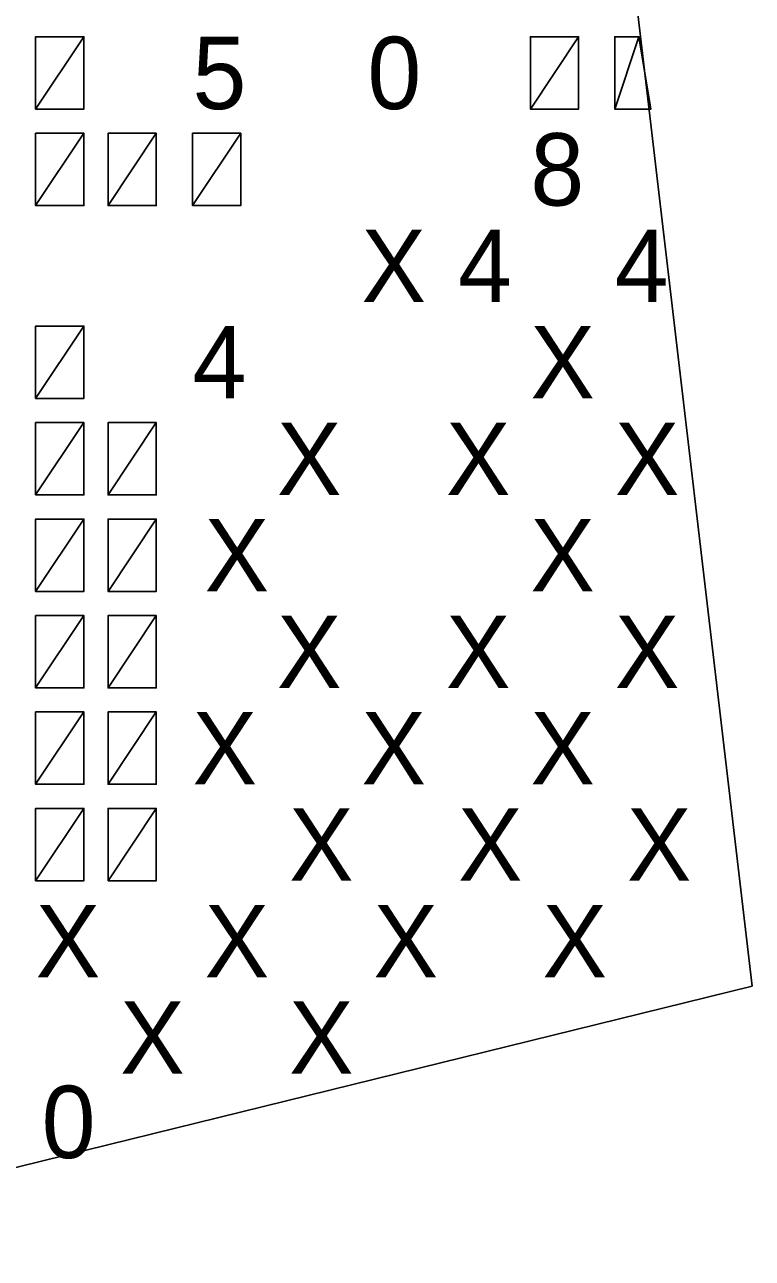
# Model space of a CAD drawing. Extents: x 0 to 34, y -1.2 to 22.
# Drawn here: x 3.5971 to 3.7687, y 4.3382 to 4.6293 of the extents above; entities that cross this region are included whole.
import ezdxf

# ---------------------------------------------------------------- set-up
doc = ezdxf.new("R2010")
doc.units = 0
doc.layers.add('Default', color=7, linetype='Continuous')

msp = doc.modelspace()

# ---------------------------------------------------------------- linework, layer by layer
at = {"layer": 'Default'}
for p, q in [((3.71021, 4.89963), (3.76865, 4.40245)), ((3.59966, 4.62644), (3.59966, 4.60937)), ((3.61104, 4.62644), (3.59966, 4.62644)), ((3.61104, 4.60937), (3.61104, 4.62644)), ((3.72769, 4.62644), (3.71631, 4.62644)), ((3.71631, 4.62644), (3.71631, 4.60937)), ((3.72769, 4.60937), (3.72769, 4.62644)), ((3.73623, 4.62644), (3.74192, 4.62644)), ((3.73623, 4.60937), (3.73623, 4.62644)), ((3.59966, 4.60937), (3.61104, 4.60937)), ((3.71631, 4.60937), (3.72769, 4.60937)), ((3.73623, 4.60937), (3.74476, 4.60937)), ((3.61104, 4.60368), (3.59966, 4.60368)), ((3.59966, 4.60368), (3.59966, 4.58661)), ((3.61104, 4.58661), (3.61104, 4.60368)), ((3.61673, 4.60368), (3.61673, 4.58661)), ((3.62811, 4.60368), (3.61673, 4.60368)), ((3.62811, 4.58661), (3.62811, 4.60368)), ((3.64803, 4.60368), (3.63665, 4.60368)), ((3.63665, 4.60368), (3.63665, 4.58661)), ((3.64803, 4.58661), (3.64803, 4.60368)), ((3.59966, 4.58661), (3.61104, 4.58661)), ((3.61673, 4.58661), (3.62811, 4.58661)), ((3.63665, 4.58661), (3.64803, 4.58661)), ((3.59966, 4.55816), (3.59966, 4.54109)), ((3.61104, 4.55816), (3.59966, 4.55816)), ((3.61104, 4.54109), (3.61104, 4.55816)), ((3.59966, 4.54109), (3.61104, 4.54109)), ((3.61104, 4.53539), (3.59966, 4.53539)), ((3.59966, 4.53539), (3.59966, 4.51832)), ((3.61104, 4.51832), (3.61104, 4.53539)), ((3.61673, 4.53539), (3.61673, 4.51832)), ((3.62811, 4.53539), (3.61673, 4.53539)), ((3.62811, 4.51832), (3.62811, 4.53539)), ((3.59966, 4.51832), (3.61104, 4.51832)), ((3.61673, 4.51832), (3.62811, 4.51832)), ((3.61104, 4.51263), (3.59966, 4.51263)), ((3.59966, 4.51263), (3.59966, 4.49556)), ((3.61104, 4.49556), (3.61104, 4.51263)), ((3.62811, 4.51263), (3.61673, 4.51263)), ((3.61673, 4.51263), (3.61673, 4.49556)), ((3.62811, 4.49556), (3.62811, 4.51263)), ((3.59966, 4.49556), (3.61104, 4.49556)), ((3.61673, 4.49556), (3.62811, 4.49556)), ((3.59966, 4.48987), (3.59966, 4.4728)), ((3.61104, 4.48987), (3.59966, 4.48987)), ((3.61104, 4.4728), (3.61104, 4.48987)), ((3.62811, 4.48987), (3.61673, 4.48987)), ((3.61673, 4.48987), (3.61673, 4.4728)), ((3.62811, 4.4728), (3.62811, 4.48987)), ((3.59966, 4.4728), (3.61104, 4.4728)), ((3.61673, 4.4728), (3.62811, 4.4728)), ((3.61104, 4.46711), (3.59966, 4.46711)), ((3.59966, 4.46711), (3.59966, 4.45004)), ((3.61104, 4.45004), (3.61104, 4.46711)), ((3.61673, 4.46711), (3.61673, 4.45004)), ((3.62811, 4.46711), (3.61673, 4.46711)), ((3.62811, 4.45004), (3.62811, 4.46711)), ((3.59966, 4.45004), (3.61104, 4.45004)), ((3.61673, 4.45004), (3.62811, 4.45004)), ((3.61104, 4.44435), (3.59966, 4.44435)), ((3.59966, 4.44435), (3.59966, 4.42728)), ((3.61104, 4.42728), (3.61104, 4.44435)), ((3.61673, 4.44435), (3.61673, 4.42728)), ((3.62811, 4.44435), (3.61673, 4.44435)), ((3.62811, 4.42728), (3.62811, 4.44435)), ((3.59966, 4.42728), (3.61104, 4.42728)), ((3.61673, 4.42728), (3.62811, 4.42728)), ((3.76865, 4.40245), (3.50784, 4.33819))]:
    msp.add_line(p, q, dxfattribs=at)
for points in [[(3.59966, 4.60937), (3.59966, 4.62644), (3.61104, 4.62644)], [(3.61104, 4.62644), (3.61104, 4.60937), (3.59966, 4.60937)], [(3.61104, 4.62644), (3.61104, 4.62644), (3.61104, 4.62644)], [(3.71631, 4.60937), (3.71631, 4.62644), (3.72769, 4.62644)], [(3.72769, 4.62644), (3.72769, 4.60937), (3.71631, 4.60937)], [(3.73623, 4.60937), (3.73623, 4.62644), (3.74192, 4.62644)], [(3.74192, 4.62644), (3.74476, 4.60937), (3.73623, 4.60937)], [(3.61104, 4.60368), (3.61104, 4.58661), (3.59966, 4.58661)], [(3.59966, 4.58661), (3.59966, 4.60368), (3.61104, 4.60368)], [(3.61104, 4.60368), (3.61104, 4.60368), (3.61104, 4.60368)], [(3.62811, 4.60368), (3.62811, 4.58661), (3.61673, 4.58661)], [(3.61673, 4.58661), (3.61673, 4.60368), (3.62811, 4.60368)], [(3.63665, 4.58661), (3.63665, 4.60368), (3.64803, 4.60368)], [(3.64803, 4.60368), (3.64803, 4.58661), (3.63665, 4.58661)], [(3.59966, 4.54109), (3.59966, 4.55816), (3.61104, 4.55816)], [(3.59966, 4.54109), (3.61104, 4.54109), (3.61104, 4.55816)], [(3.59966, 4.51832), (3.61104, 4.51832), (3.61104, 4.53539)], [(3.59966, 4.51832), (3.59966, 4.53539), (3.61104, 4.53539)], [(3.62811, 4.53539), (3.62811, 4.51832), (3.61673, 4.51832)], [(3.61673, 4.51832), (3.61673, 4.53539), (3.62811, 4.53539)], [(3.59966, 4.49556), (3.61104, 4.49556), (3.61104, 4.51263)], [(3.59966, 4.49556), (3.59966, 4.51263), (3.61104, 4.51263)], [(3.61673, 4.49556), (3.61673, 4.51263), (3.62811, 4.51263)], [(3.62811, 4.51263), (3.62811, 4.49556), (3.61673, 4.49556)], [(3.59966, 4.4728), (3.59966, 4.48987), (3.61104, 4.48987)], [(3.61104, 4.48987), (3.61104, 4.4728), (3.59966, 4.4728)], [(3.61104, 4.48987), (3.61104, 4.48987), (3.61104, 4.48987)], [(3.61673, 4.4728), (3.61673, 4.48987), (3.62811, 4.48987)], [(3.62811, 4.48987), (3.62811, 4.4728), (3.61673, 4.4728)], [(3.61104, 4.46711), (3.61104, 4.45004), (3.59966, 4.45004)], [(3.59966, 4.45004), (3.59966, 4.46711), (3.61104, 4.46711)], [(3.61104, 4.46711), (3.61104, 4.46711), (3.61104, 4.46711)], [(3.62811, 4.46711), (3.62811, 4.45004), (3.61673, 4.45004)], [(3.61673, 4.45004), (3.61673, 4.46711), (3.62811, 4.46711)], [(3.59966, 4.42728), (3.59966, 4.44435), (3.61104, 4.44435)], [(3.61104, 4.44435), (3.61104, 4.42728), (3.59966, 4.42728)], [(3.61673, 4.42728), (3.61673, 4.44435), (3.62811, 4.44435)], [(3.61673, 4.42728), (3.62811, 4.42728), (3.62811, 4.44435)]]:
    msp.add_lwpolyline(points, close=True, dxfattribs=at)

# ---------------------------------------------------------------- texts
for s, p in [('5', (3.63665, 4.60937)), ('0', (3.6779, 4.60937)), ('8', (3.71631, 4.58661)), ('X', (3.67648, 4.56385)), ('4', (3.69924, 4.56385)), ('4', (3.73623, 4.56385)), ('4', (3.63665, 4.54109)), ('X', (3.71631, 4.54109)), ('X', (3.65656, 4.51832)), ('X', (3.6964, 4.51832)), ('X', (3.73623, 4.51832)), ('X', (3.63949, 4.49556)), ('X', (3.71631, 4.49556)), ('X', (3.65656, 4.4728)), ('X', (3.6964, 4.4728)), ('X', (3.73623, 4.4728)), ('X', (3.63665, 4.45004)), ('X', (3.67648, 4.45004)), ('X', (3.71631, 4.45004)), ('X', (3.65941, 4.42728)), ('X', (3.69924, 4.42728)), ('X', (3.73907, 4.42728)), ('X', (3.59966, 4.40452)), ('X', (3.63949, 4.40452)), ('X', (3.67932, 4.40452)), ('X', (3.71916, 4.40452)), ('X', (3.61958, 4.38175)), ('X', (3.65941, 4.38175)), ('0', (3.60108, 4.36184))]:
    msp.add_text(s, height=0.01707, dxfattribs=at).set_placement(p)

doc.saveas('drawing.dxf')
